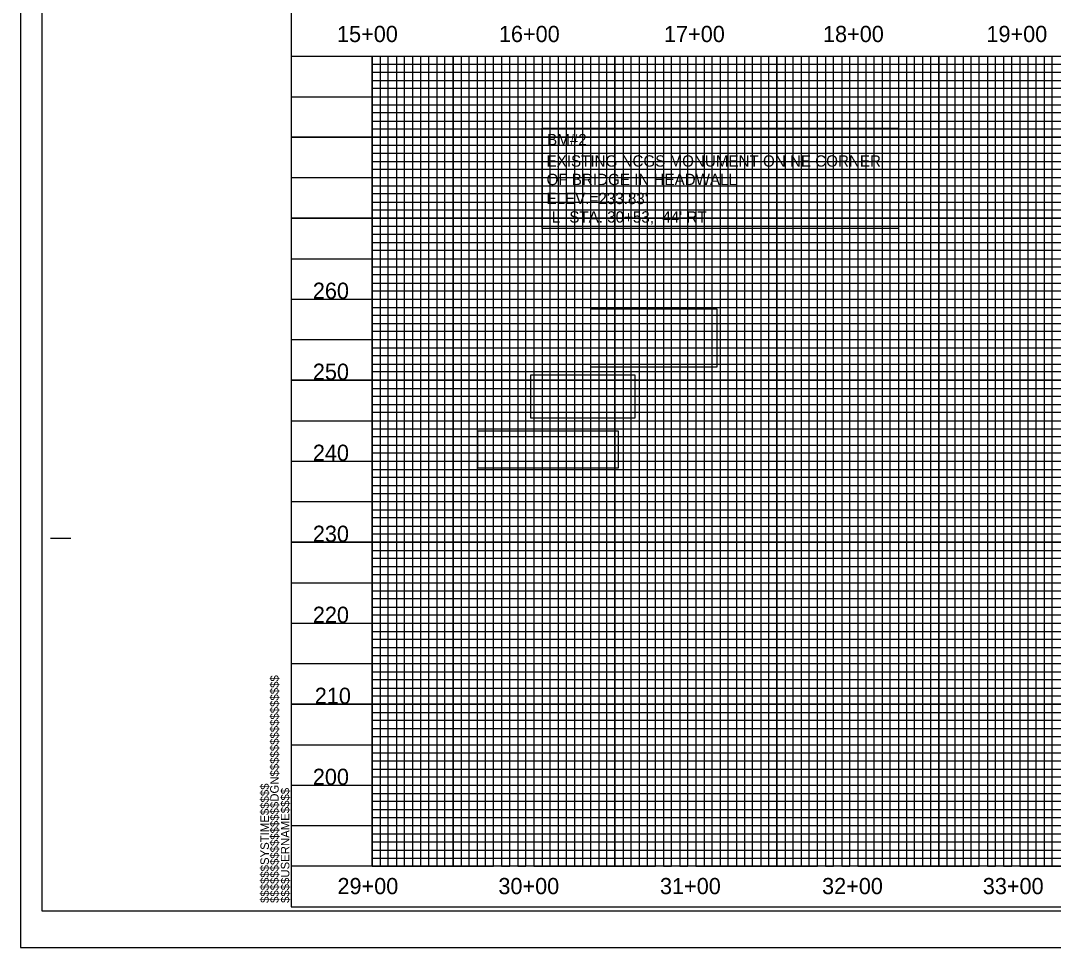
# Model space of a CAD drawing. Extents: x 1810963 to 1812948, y 722070 to 723250.
# Drawn here: x 1810963 to 1811601, y 722070 to 722642 of the extents above; entities that cross this region are included whole.
import ezdxf

# ---------------------------------------------------------------- set-up
doc = ezdxf.new("R2010")
doc.units = 0
for name, color, linetype in [('Exist Vertical Profile Horizontal Axis Label Major', 7, 'Continuous'), ('Exist Vertical Profile Vertical Axis Label', 7, 'Continuous'), ('Prop Grid Mask', 7, 'Continuous'), ('Prop Horizontal Alignment Station Label', 7, 'Continuous'), ('Sheet Cutting Line CELL', 7, 'Continuous'), ('Sheet DOT Grid CELL', 7, 'Continuous'), ('Sheet Layout Profile Border Port 2', 7, 'Continuous'), ('Sheet Plot Border Inside CELL', 7, 'Continuous'), ('Sheet Plot Border Outside CELL', 7, 'Continuous'), ('Sheet Profile CELL', 7, 'Continuous'), ('Sheet Profile Grid Major CELL', 7, 'Continuous'), ('Sheet Profile Grid Middle CELL', 7, 'Continuous'), ('Sheet Profile Grid Minor CELL', 7, 'Continuous')]:
    doc.layers.add(name, color=color, linetype=linetype)

msp = doc.modelspace()

# ---------------------------------------------------------------- linework, layer by layer
at = {"layer": 'Prop Grid Mask'}
for points in [[(1811285.45, 722575.53), (1811505.47, 722575.53), (1811505.47, 722513.58), (1811285.45, 722513.58)], [(1811315.59, 722464.06), (1811393.33, 722464.06), (1811393.33, 722427.99), (1811315.59, 722427.99)], [(1811278.41, 722423.27), (1811342.69, 722423.27), (1811342.69, 722396.39), (1811278.41, 722396.39)], [(1811245.83, 722388.76), (1811332.37, 722388.76), (1811332.37, 722365.69), (1811245.83, 722365.69)]]:
    msp.add_lwpolyline(points, close=True, dxfattribs=at)
at = {"layer": 'Sheet Cutting Line CELL'}
for p, q in [((1810963.46, 723169.88), (1810963.46, 722069.88)), ((1810963.46, 722069.88), (1812647.46, 722069.88))]:
    msp.add_line(p, q, dxfattribs=at)
at = {"layer": 'Sheet DOT Grid CELL'}
for p, q in [((1811130.46, 722619.88), (1812630.35, 722619.88)), ((1811180.46, 722619.88), (1811180.46, 722119.88)), ((1811230.46, 722619.88), (1811230.46, 722119.88)), ((1811280.46, 722619.88), (1811280.46, 722119.88)), ((1811330.46, 722619.88), (1811330.46, 722119.88)), ((1811380.46, 722619.88), (1811380.46, 722119.88)), ((1811430.46, 722619.88), (1811430.46, 722119.88)), ((1811480.46, 722619.88), (1811480.46, 722119.88)), ((1811530.46, 722619.88), (1811530.46, 722119.88)), ((1811580.46, 722619.88), (1811580.46, 722119.88)), ((1811130.46, 722569.88), (1812630.35, 722569.88)), ((1811130.46, 722519.88), (1812630.35, 722519.88)), ((1811130.46, 722469.88), (1812630.35, 722469.88)), ((1811130.46, 722419.88), (1812630.35, 722419.88)), ((1811130.46, 722369.88), (1812630.35, 722369.88)), ((1811130.46, 722319.88), (1812630.35, 722319.88)), ((1811130.46, 722269.88), (1812630.35, 722269.88)), ((1811130.46, 722219.88), (1812630.35, 722219.88)), ((1811130.46, 722169.88), (1812630.35, 722169.88))]:
    msp.add_line(p, q, dxfattribs=at)
at = {"layer": 'Sheet Layout Profile Border Port 2'}
msp.add_lwpolyline([(1811180.46, 722619.88), (1812580.46, 722619.88), (1812580.46, 722119.88), (1811180.46, 722119.88)], close=True, dxfattribs=at)
at = {"layer": 'Sheet Plot Border Inside CELL'}
msp.add_lwpolyline([(1810976.46, 722092.33), (1812642.96, 722092.33), (1812642.96, 723147.43), (1810976.46, 723147.43)], close=True, dxfattribs=at)
at = {"layer": 'Sheet Plot Border Outside CELL'}
msp.add_lwpolyline([(1810963.46, 722069.88), (1812647.46, 722069.88), (1812647.46, 723169.88), (1810963.46, 723169.88)], close=True, dxfattribs=at)
at = {"layer": 'Sheet Profile CELL'}
for p, q in [((1811130.46, 722619.88), (1812630.46, 722619.88)), ((1810981.96, 722322.38), (1810994.46, 722322.38)), ((1812630.46, 722119.88), (1811130.46, 722119.88)), ((1811130.46, 722094.88), (1812630.46, 722094.88)), ((1811130.46, 722094.88), (1811130.46, 722094.88)), ((1811130.46, 722094.88), (1811130.46, 722094.88)), ((1811130.46, 722094.88), (1811130.46, 722094.88)), ((1811130.46, 722094.88), (1811130.46, 722094.88)), ((1811130.46, 722094.88), (1811130.46, 722094.88)), ((1811130.46, 722094.88), (1811130.46, 722094.88)), ((1811130.46, 722094.88), (1811130.46, 722094.88))]:
    msp.add_line(p, q, dxfattribs=at)
msp.add_lwpolyline([(1812630.46, 723144.88), (1811130.46, 723144.88), (1811130.46, 722094.88), (1812630.46, 722094.88)], close=True, dxfattribs=at)
msp.add_lwpolyline([(1811160.99, 722094.88), (1811160.99, 722094.88)], dxfattribs=at)
at = {"layer": 'Sheet Profile Grid Major CELL'}
msp.add_line((1811130.46, 722119.88), (1811130.46, 722119.88), dxfattribs=at)
for points in [[(1811180.46, 722619.88), (1811180.46, 722119.88), (1811230.46, 722119.88), (1811230.46, 722619.88), (1811280.46, 722619.88), (1811280.46, 722119.88), (1811330.46, 722119.88), (1811330.46, 722619.88), (1811380.46, 722619.88), (1811380.46, 722119.88), (1811430.46, 722119.88), (1811430.46, 722619.88), (1811480.46, 722619.88), (1811480.46, 722119.88), (1811530.46, 722119.88), (1811530.46, 722619.88), (1811580.46, 722619.88), (1811580.46, 722119.88), (1811630.46, 722119.88)], [(1812630.46, 722569.88), (1811130.46, 722569.88)], [(1812630.46, 722519.88), (1811130.46, 722519.88), (1811130.46, 722469.88), (1812630.46, 722469.88)], [(1812630.46, 722419.88), (1811130.46, 722419.88), (1811130.46, 722369.88), (1812630.46, 722369.88)], [(1812630.46, 722319.88), (1811130.46, 722319.88), (1811130.46, 722269.88), (1812630.46, 722269.88)], [(1812630.46, 722219.88), (1811130.46, 722219.88), (1811130.46, 722219.88), (1811130.46, 722169.88), (1812630.46, 722169.88)], [(1812630.46, 722119.88), (1811130.46, 722119.88)]]:
    msp.add_lwpolyline(points, dxfattribs=at)
at = {"layer": 'Sheet Profile Grid Middle CELL'}
for points in [[(1811155.46, 722619.88), (1811205.46, 722619.88), (1811205.46, 722119.88), (1811255.46, 722119.88), (1811255.46, 722619.88), (1811305.46, 722619.88), (1811305.46, 722119.88), (1811355.46, 722119.88), (1811355.46, 722619.88), (1811405.46, 722619.88), (1811405.46, 722119.88), (1811455.46, 722119.88), (1811455.46, 722619.88), (1811505.46, 722619.88), (1811505.46, 722119.88), (1811555.46, 722119.88), (1811555.46, 722619.88), (1811605.46, 722619.88)], [(1811130.46, 722594.88), (1812630.46, 722594.88)], [(1812630.46, 722544.88), (1811130.46, 722544.88), (1811130.46, 722494.88), (1812630.46, 722494.88)], [(1812630.46, 722444.88), (1811130.46, 722444.88), (1811130.46, 722394.88), (1812630.46, 722394.88)], [(1812630.46, 722344.88), (1811130.46, 722344.88), (1811130.46, 722294.88), (1812630.46, 722294.88)], [(1812630.46, 722244.88), (1811130.46, 722244.88), (1811130.46, 722194.88), (1812630.46, 722194.88)], [(1812630.46, 722144.88), (1811130.46, 722144.88)]]:
    msp.add_lwpolyline(points, dxfattribs=at)
at = {"layer": 'Sheet Profile Grid Minor CELL'}
for p, q in [((1811180.46, 722614.88), (1812580.46, 722614.88)), ((1812580.46, 722609.88), (1811180.46, 722609.88)), ((1811180.46, 722604.88), (1812580.46, 722604.88)), ((1812580.46, 722599.88), (1811180.46, 722599.88)), ((1811180.46, 722589.88), (1812580.46, 722589.88)), ((1812580.46, 722584.88), (1811180.46, 722584.88)), ((1811180.46, 722579.88), (1812580.46, 722579.88)), ((1812580.46, 722574.88), (1811180.46, 722574.88)), ((1811180.46, 722564.88), (1812580.46, 722564.88)), ((1812580.46, 722559.88), (1811180.46, 722559.88)), ((1811180.46, 722554.88), (1812580.46, 722554.88)), ((1812580.46, 722549.88), (1811180.46, 722549.88)), ((1811180.46, 722539.88), (1812580.46, 722539.88)), ((1812580.46, 722534.88), (1811180.46, 722534.88)), ((1811180.46, 722529.88), (1812580.46, 722529.88)), ((1812580.46, 722524.88), (1811180.46, 722524.88)), ((1811180.46, 722514.88), (1812580.46, 722514.88)), ((1812580.46, 722509.88), (1811180.46, 722509.88)), ((1811180.46, 722504.88), (1812580.46, 722504.88)), ((1812580.46, 722499.88), (1811180.46, 722499.88)), ((1811180.46, 722489.88), (1812580.46, 722489.88)), ((1812580.46, 722484.88), (1811180.46, 722484.88)), ((1811180.46, 722479.88), (1812580.46, 722479.88)), ((1812580.46, 722474.88), (1811180.46, 722474.88)), ((1811180.46, 722464.88), (1812580.46, 722464.88)), ((1812580.46, 722459.88), (1811180.46, 722459.88)), ((1811180.46, 722454.88), (1812580.46, 722454.88)), ((1812580.46, 722449.88), (1811180.46, 722449.88)), ((1811180.46, 722439.88), (1812580.46, 722439.88)), ((1812580.46, 722434.88), (1811180.46, 722434.88)), ((1811180.46, 722429.88), (1812580.46, 722429.88)), ((1812580.46, 722424.88), (1811180.46, 722425.03)), ((1811180.46, 722414.88), (1812580.46, 722414.88)), ((1812580.46, 722409.88), (1811180.46, 722409.88)), ((1811180.46, 722404.88), (1812580.46, 722404.88)), ((1812580.46, 722399.88), (1811180.46, 722399.88)), ((1811180.46, 722389.88), (1812580.46, 722389.88)), ((1812580.46, 722384.88), (1811180.46, 722384.88)), ((1811180.46, 722379.88), (1812580.46, 722379.88)), ((1812580.46, 722374.88), (1811180.46, 722374.88)), ((1811180.46, 722364.88), (1812580.46, 722364.88)), ((1812580.46, 722359.88), (1811180.46, 722359.88)), ((1811180.46, 722354.88), (1812580.46, 722354.88)), ((1812580.46, 722349.88), (1811180.46, 722349.88)), ((1811180.46, 722339.88), (1812580.46, 722339.88)), ((1812580.46, 722334.88), (1811180.46, 722334.88)), ((1811180.46, 722329.88), (1812580.46, 722329.88)), ((1812580.46, 722324.88), (1811180.46, 722324.88)), ((1811180.46, 722314.88), (1812580.46, 722314.88)), ((1812580.46, 722309.88), (1811180.46, 722309.88)), ((1811180.46, 722304.88), (1812580.46, 722304.88)), ((1812580.46, 722299.88), (1811180.46, 722299.88)), ((1811180.46, 722289.88), (1812580.46, 722289.88)), ((1812580.46, 722284.88), (1811180.46, 722284.88)), ((1811180.46, 722279.88), (1812580.46, 722279.88)), ((1812580.46, 722274.88), (1811180.46, 722274.88)), ((1811180.46, 722264.88), (1812580.46, 722264.88)), ((1812580.46, 722259.88), (1811180.46, 722259.88)), ((1811180.46, 722254.88), (1812580.46, 722254.88)), ((1812580.46, 722249.88), (1811180.46, 722249.88)), ((1811180.46, 722239.88), (1812580.46, 722239.88)), ((1812580.46, 722234.88), (1811180.46, 722234.88)), ((1811180.46, 722229.88), (1812580.46, 722229.88)), ((1812580.46, 722224.88), (1811180.46, 722224.88)), ((1811180.46, 722214.88), (1812580.46, 722214.88)), ((1812580.46, 722209.88), (1811180.46, 722209.88)), ((1811180.46, 722204.88), (1812580.46, 722204.88)), ((1812580.46, 722199.88), (1811180.46, 722199.88)), ((1811180.46, 722189.88), (1812580.46, 722189.88)), ((1812580.46, 722184.88), (1811180.46, 722184.88)), ((1811180.46, 722179.88), (1812580.46, 722179.88)), ((1812580.46, 722174.88), (1811180.46, 722174.88)), ((1811180.46, 722164.88), (1812580.46, 722164.88)), ((1812580.46, 722159.88), (1811180.46, 722159.88)), ((1811180.46, 722154.88), (1812580.46, 722154.88)), ((1812580.46, 722149.88), (1811180.46, 722149.88)), ((1811180.46, 722139.88), (1812580.46, 722139.88)), ((1812580.46, 722134.88), (1811180.46, 722134.88)), ((1811180.46, 722129.88), (1812580.46, 722129.88)), ((1811180.46, 722124.88), (1812580.46, 722124.88))]:
    msp.add_line(p, q, dxfattribs=at)
for points in [[(1811180.46, 722619.88), (1811185.46, 722619.88), (1811185.46, 722119.88), (1811190.46, 722119.88), (1811190.46, 722619.88), (1811195.46, 722619.88), (1811195.46, 722119.88), (1811200.46, 722119.88), (1811200.46, 722619.88), (1811210.46, 722619.88), (1811210.46, 722119.88), (1811215.46, 722119.88), (1811215.46, 722619.88), (1811220.46, 722619.88), (1811220.46, 722119.88), (1811225.46, 722119.88), (1811235.46, 722119.88), (1811240.46, 722119.88), (1811240.46, 722619.88), (1811245.46, 722619.88), (1811245.46, 722119.88), (1811250.46, 722119.88), (1811250.46, 722619.88), (1811260.46, 722619.88), (1811260.46, 722119.88), (1811265.46, 722119.88), (1811265.46, 722619.88), (1811270.46, 722619.88), (1811270.46, 722119.88), (1811275.46, 722119.88), (1811275.46, 722619.88), (1811285.46, 722619.88), (1811285.46, 722119.88), (1811290.46, 722119.88), (1811290.46, 722619.88), (1811295.46, 722619.88), (1811295.46, 722119.88), (1811300.46, 722119.88), (1811300.46, 722619.88), (1811310.46, 722619.88), (1811310.46, 722119.88), (1811315.46, 722119.88), (1811315.46, 722619.88), (1811320.46, 722619.88), (1811320.46, 722119.88), (1811325.46, 722119.88), (1811325.46, 722619.88), (1811335.46, 722619.88), (1811335.46, 722119.88), (1811340.46, 722119.88), (1811340.46, 722619.88), (1811345.46, 722619.88), (1811345.46, 722119.88), (1811350.46, 722119.88), (1811350.46, 722619.88), (1811360.46, 722619.88), (1811360.46, 722119.88), (1811365.46, 722119.88), (1811365.46, 722619.88), (1811370.46, 722619.88), (1811370.46, 722119.88), (1811375.46, 722119.88), (1811375.46, 722619.88), (1811385.46, 722619.88), (1811385.46, 722119.88), (1811390.46, 722119.88), (1811390.46, 722619.88), (1811395.46, 722619.88), (1811395.46, 722119.88)], [(1811225.46, 722119.88), (1811225.46, 722619.88), (1811235.46, 722619.88), (1811235.46, 722119.88)], [(1811395.46, 722119.88), (1811400.46, 722119.88), (1811400.46, 722619.88), (1811410.46, 722619.88), (1811410.46, 722119.88), (1811415.46, 722119.88), (1811415.46, 722619.88), (1811420.46, 722619.88), (1811420.46, 722119.88), (1811425.46, 722119.88), (1811425.46, 722619.88), (1811435.46, 722619.88), (1811435.46, 722119.88), (1811440.46, 722119.88), (1811440.46, 722619.88), (1811445.46, 722619.88), (1811445.46, 722119.88), (1811450.46, 722119.88), (1811450.46, 722619.88), (1811460.46, 722619.88), (1811460.46, 722119.88), (1811465.46, 722119.88), (1811465.46, 722619.88), (1811470.46, 722619.88), (1811470.46, 722119.88), (1811475.46, 722119.88), (1811475.46, 722619.88), (1811485.46, 722619.88), (1811485.46, 722119.88), (1811490.46, 722119.88), (1811490.46, 722619.88), (1811495.46, 722619.88), (1811495.46, 722119.88), (1811500.46, 722119.88), (1811500.46, 722619.88), (1811510.46, 722619.88), (1811510.46, 722119.88), (1811515.46, 722119.88), (1811515.46, 722619.88), (1811520.46, 722619.88), (1811520.46, 722119.88), (1811525.46, 722119.88), (1811525.46, 722619.88), (1811535.46, 722619.88), (1811535.46, 722119.88), (1811540.46, 722119.88), (1811540.46, 722619.88), (1811545.46, 722619.88), (1811545.46, 722119.88), (1811550.46, 722119.88), (1811550.46, 722619.88), (1811560.46, 722619.88), (1811560.46, 722119.88), (1811565.46, 722119.88), (1811565.46, 722619.88), (1811570.46, 722619.88), (1811570.46, 722119.88), (1811575.46, 722119.88), (1811575.46, 722619.88), (1811585.46, 722619.88), (1811585.46, 722119.88), (1811590.46, 722119.88), (1811590.46, 722619.88), (1811595.46, 722619.88), (1811595.46, 722119.88), (1811600.46, 722119.88), (1811600.46, 722619.88), (1811610.46, 722619.88)]]:
    msp.add_lwpolyline(points, dxfattribs=at)

# ---------------------------------------------------------------- texts
at = {"layer": 'Exist Vertical Profile Horizontal Axis Label Major'}
for s, p in [('15+00', (1811158.83, 722628.6)), ('16+00', (1811258.78, 722628.6)), ('17+00', (1811360.74, 722628.6)), ('18+00', (1811458.92, 722628.6)), ('19+00', (1811559.84, 722628.6)), ('29+00', (1811159.1, 722102.7)), ('30+00', (1811258.47, 722102.7)), ('31+00', (1811358.25, 722102.7)), ('32+00', (1811458.35, 722102.7)), ('33+00', (1811557.61, 722102.7))]:
    msp.add_text(s, height=10, dxfattribs=at).set_placement(p)
at = {"layer": 'Exist Vertical Profile Vertical Axis Label'}
for s, p in [('260', (1811143.89, 722470.13)), ('250', (1811143.89, 722420.13)), ('240', (1811143.89, 722370.13)), ('230', (1811143.89, 722320.13)), ('220', (1811143.89, 722270.13)), ('210', (1811145.09, 722220.13)), ('200', (1811143.89, 722170.13))]:
    msp.add_text(s, height=10, dxfattribs=at).set_placement(p)
at = {"layer": 'Prop Horizontal Alignment Station Label'}
for s, p in [('BM#2', (1811288.53, 722564.91)), ('EXISTING NCGS MONUMENT ON NE CORNER', (1811288.22, 722551.71)), ('OF BRIDGE IN HEADWALL', (1811288.22, 722540.33)), ("ELEV.=233.83'", (1811288.22, 722528.58)), ("-L- STA. 30+53,  44' RT", (1811288.22, 722517.17))]:
    msp.add_text(s, height=7, dxfattribs=at).set_placement(p)
at = {"layer": 'Sheet Profile CELL'}
for s, p in [('$$$$$$$$$$$$$$$$DGN$$$$$$$$$$$$$$$$', (1811122.82, 722097.26)), ('$$$$$$SYSTIME$$$$$', (1811116.77, 722097.26)), ('$$$$USERNAME$$$$', (1811129.4, 722097.27))]:
    msp.add_text(s, height=5.25, rotation=90, dxfattribs=at).set_placement(p)

doc.saveas('drawing.dxf')
